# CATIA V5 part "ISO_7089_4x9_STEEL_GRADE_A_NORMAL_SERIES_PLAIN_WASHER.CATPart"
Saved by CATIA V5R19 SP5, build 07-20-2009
Part number: ISO 7089 WASHER 4x9 STEEL GRADE A PLAIN NORMAL SERIES
Publications: "Mating Face", "Axis"
Bounding box of the stored display mesh (mm): x 0 to 0.8, y -4.5 to 4.5, z -4.5 to 4.5
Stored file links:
  Z:\UA\ATLAS\atlascar\ServoPiloto\dir\suportePotenciometro\V2\ISO_7089_4x9_STEEL_GRADE_A_NORMAL_SERIES_PLAIN_WASHER.CATPart
  Z:\programs_vbox\Dassault Systemes\B19\intel_a\startup\components\MechanicalStandardParts\ISO_Standards\Design_Tables\ISO_7089_PLAIN_WASHER_GRADE_A_NORMAL_SERIES.txt
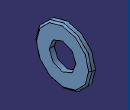
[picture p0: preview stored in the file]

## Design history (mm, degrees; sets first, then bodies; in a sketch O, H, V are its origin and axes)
Parameters
  d1_inside_dia = 4.3 mm
  d2_outside_dia = 9 mm
  h_thick = 0.8 mm
  Nominal_dia = 4 mm
Body1 "PartBody" (main body)
  Sketch1 on yz-plane, origin (0, 0, 0), H (0, 1, 0), V (0, 0, 1)
    circle A1 centre (0, 0) radius 4.5
    circle A2 centre (0, 0) radius 2.15
    radius A1 = 4.5 {= d2_outside_dia /2}
    radius A2 = 2.15 {= d1_inside_dia /2}
  Pad1: profile Sketch1, direction (1, 0, 0), length 0.8 {= h_thick}
  Chamfer1: length 0.3 {= 0.375*h_thick}, angle 37.5, on edge [face of Pad1 | face of Pad1]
